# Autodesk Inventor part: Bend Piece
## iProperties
Created: 2010-02
Part Number: Bend Piece
Document SubType Name: Modeling
Designer: jgehrig
Density: 1 g/cm^3
Author: jgehrig
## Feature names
1. Extrusion1
2. Extrusion2
3. Extrusion3
4. Extrusion4
5. Extrusion5
6. Fillet1
7. Fillet2
